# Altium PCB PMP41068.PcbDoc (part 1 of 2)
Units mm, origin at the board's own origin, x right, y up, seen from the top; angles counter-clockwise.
Board outline 71 x 50.75 mm, 4 copper layers (Top Layer, 02IS01, 03IS02, Bottom Layer), stack 0.651 mm thick; 102 components, 48 nets, 246 pads, 360 vias.
Unrouted connection lines stored in the file: 1.
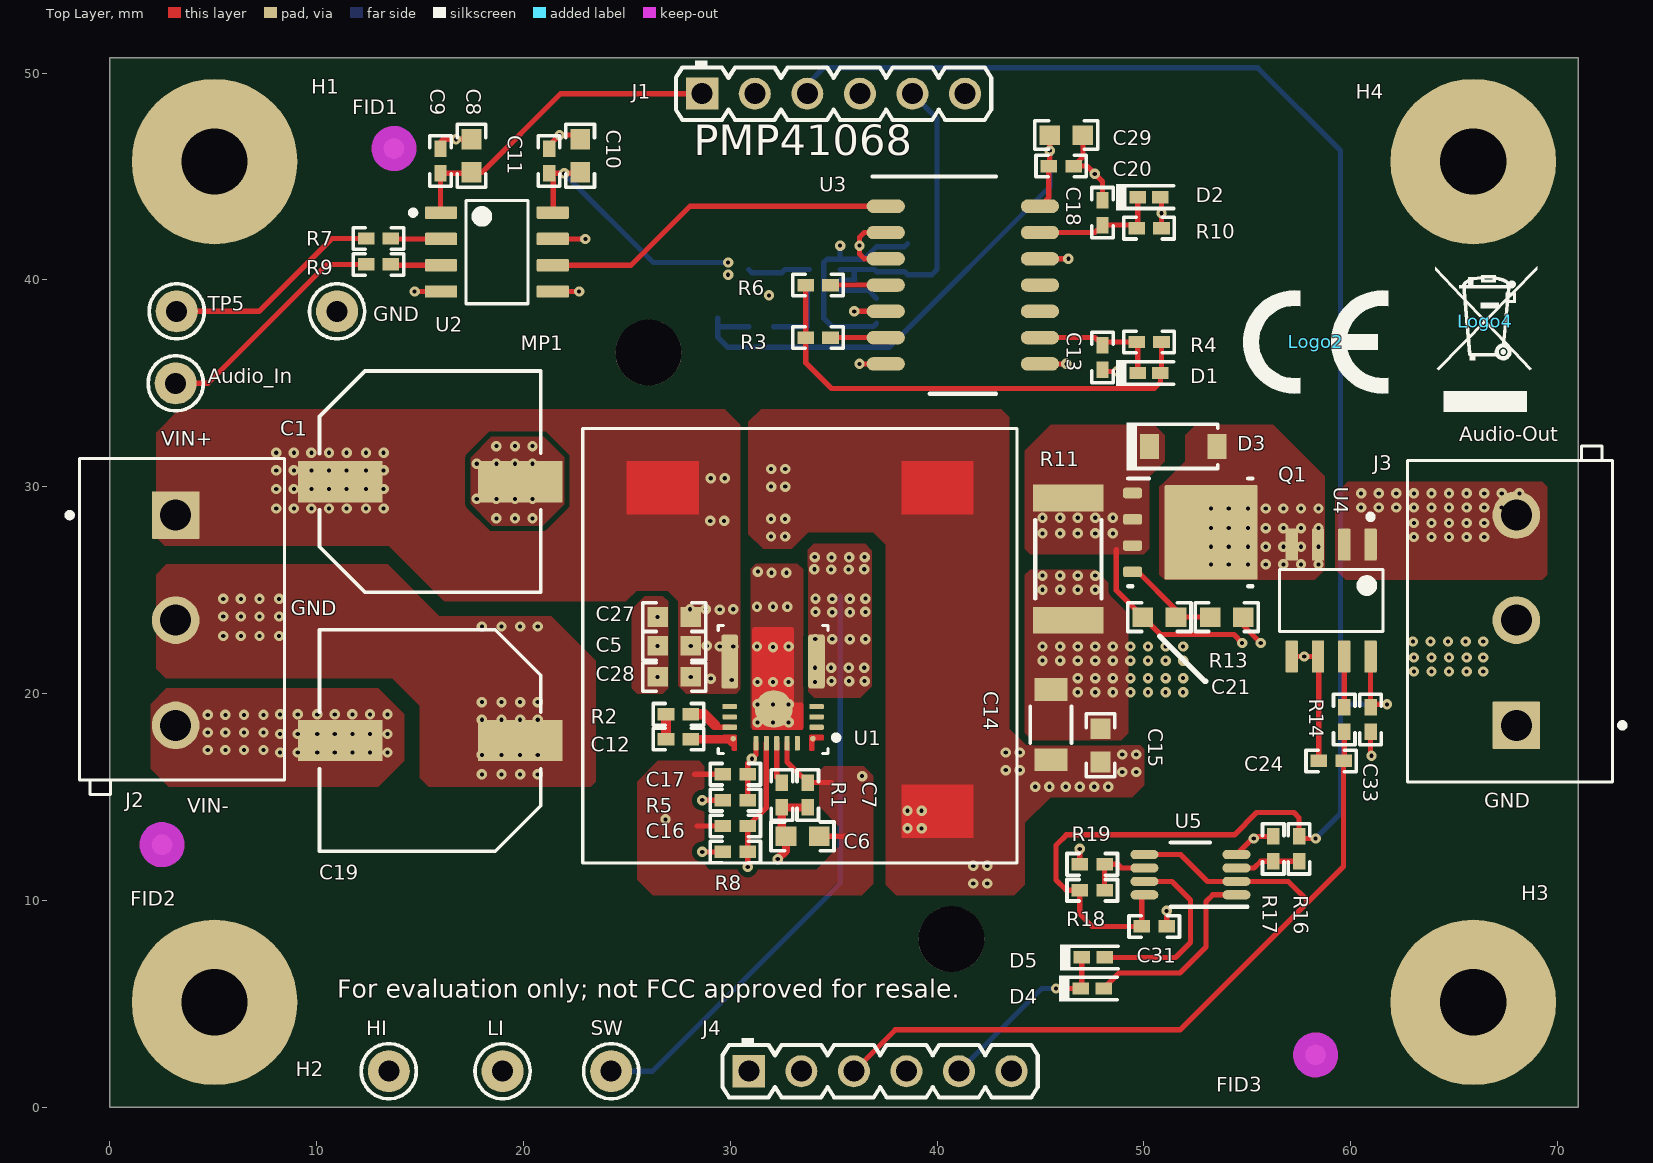
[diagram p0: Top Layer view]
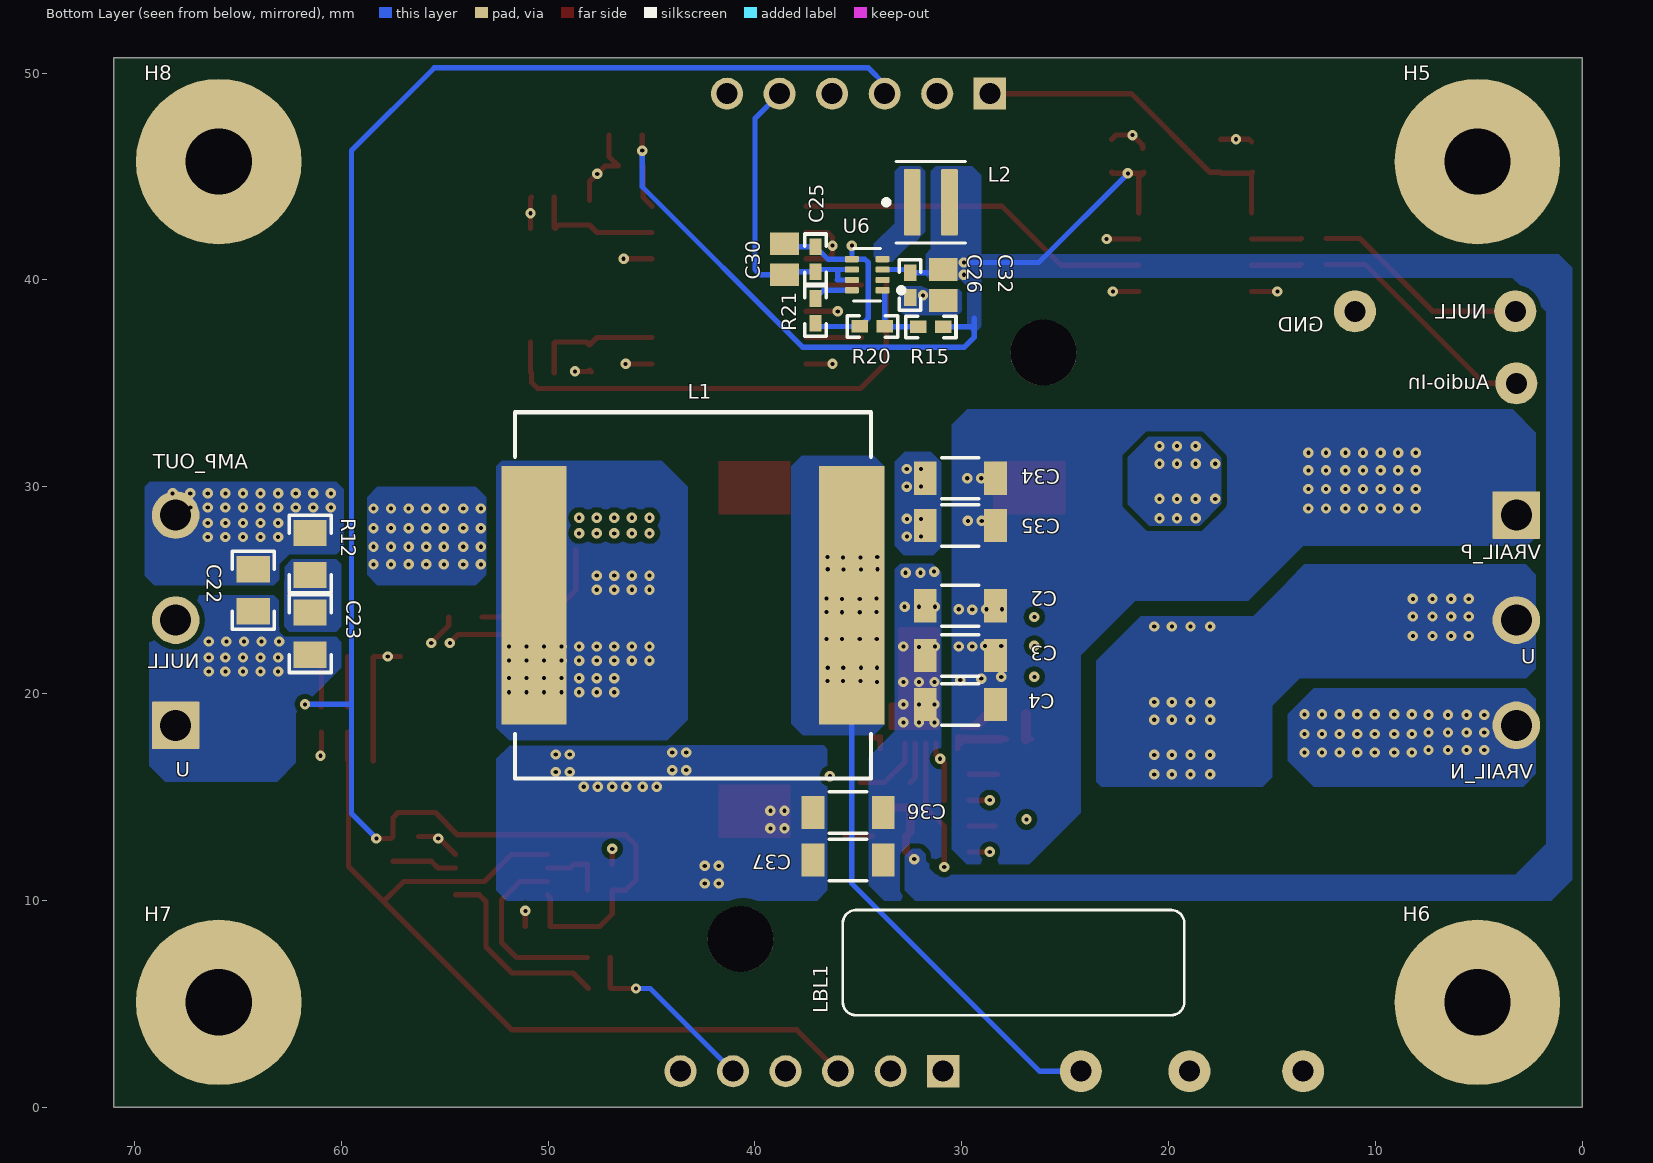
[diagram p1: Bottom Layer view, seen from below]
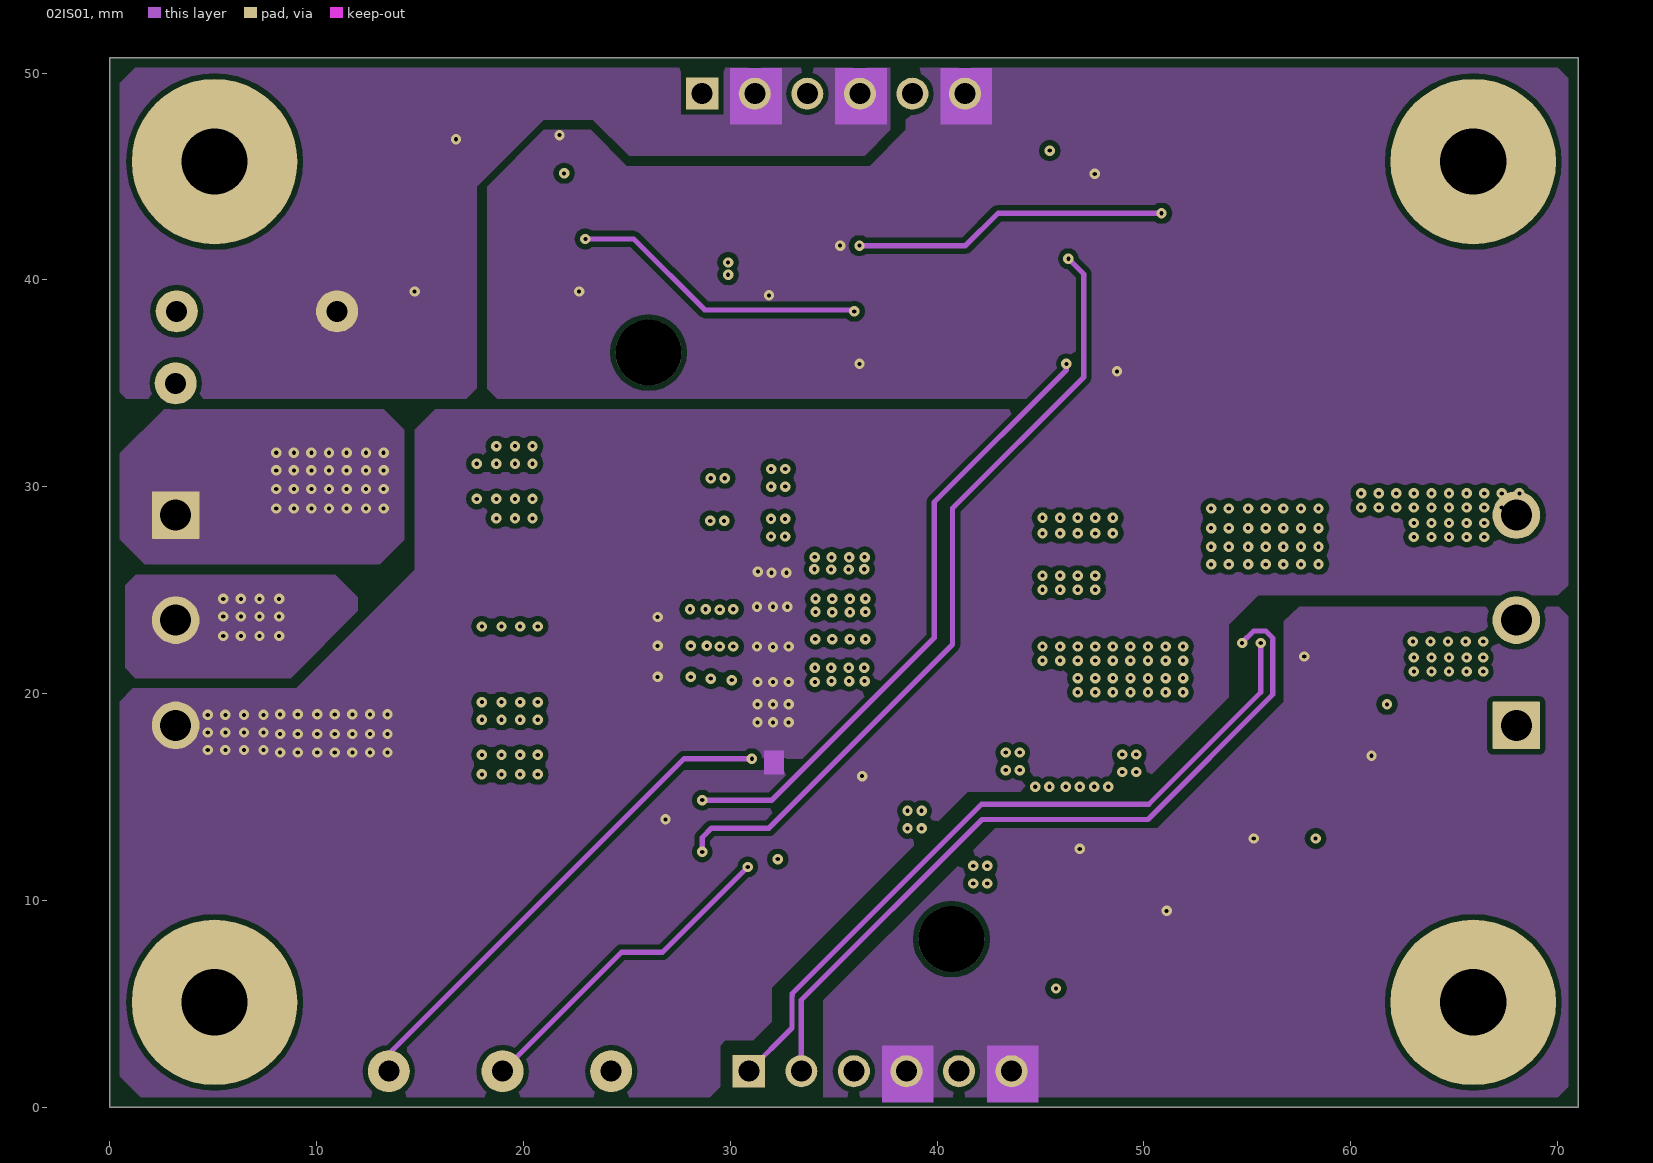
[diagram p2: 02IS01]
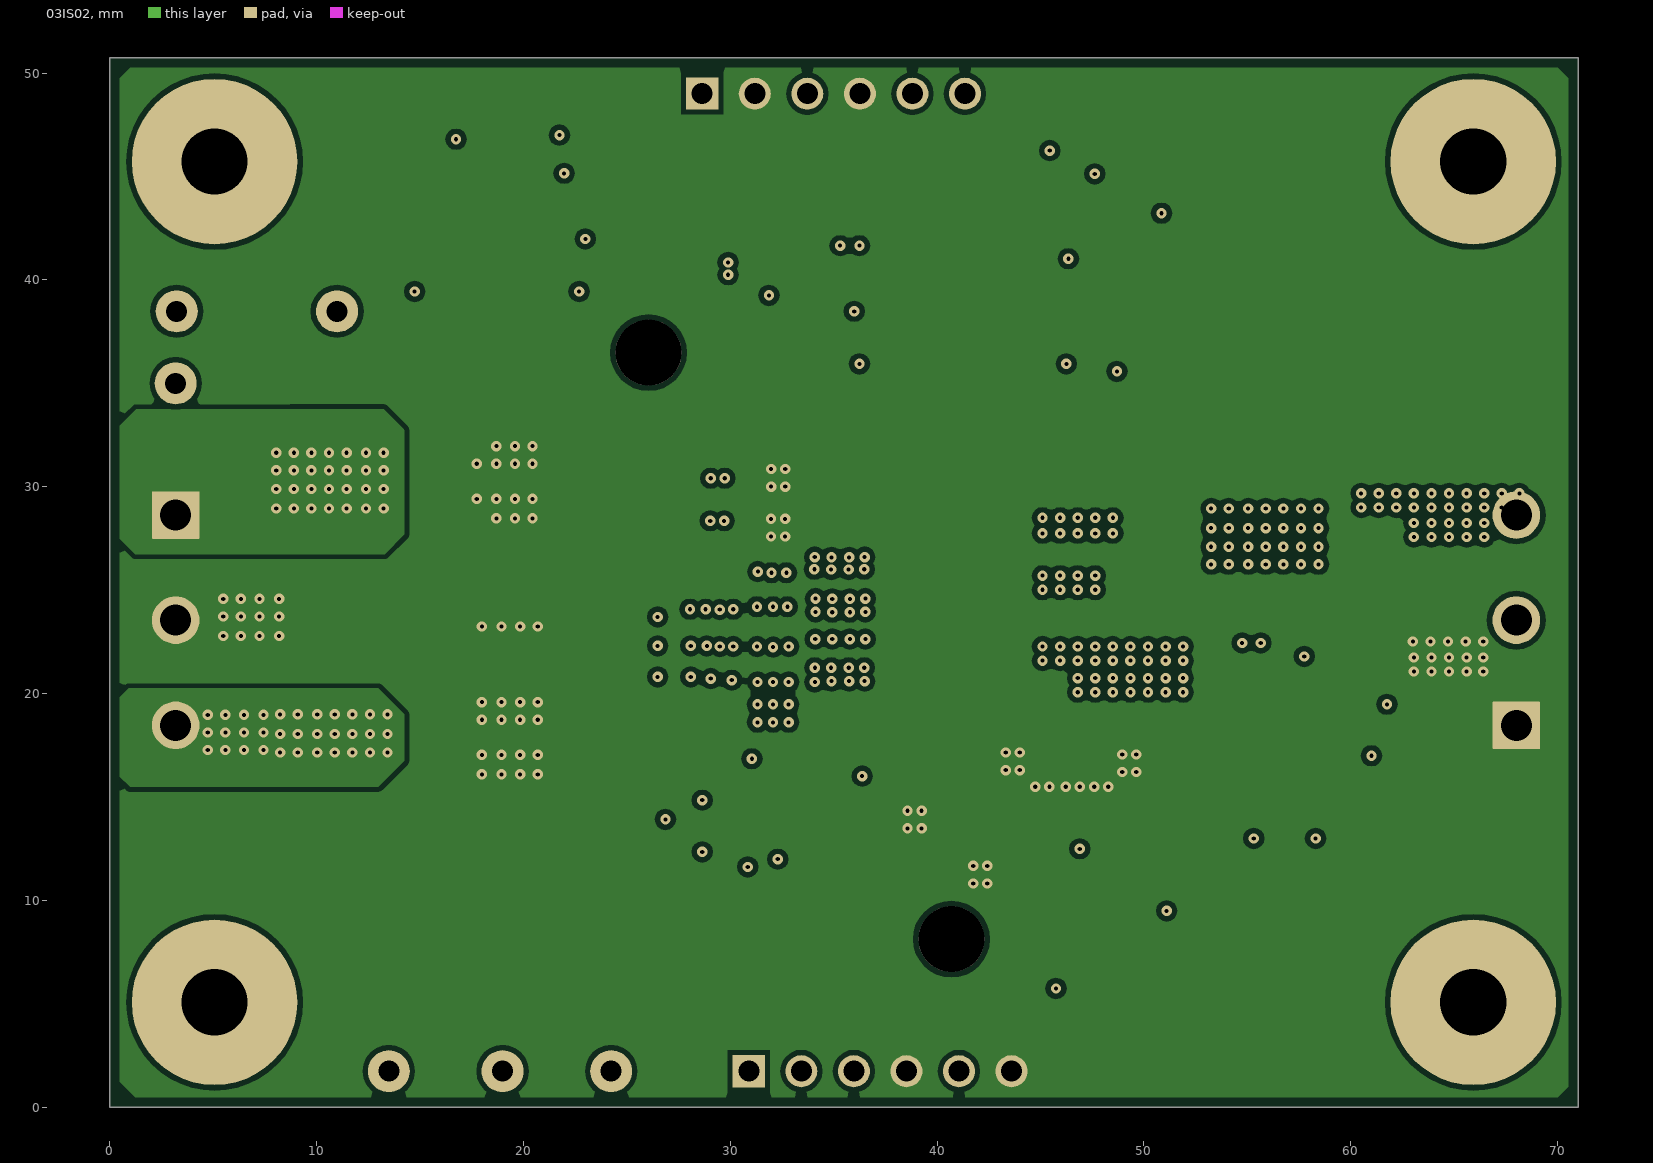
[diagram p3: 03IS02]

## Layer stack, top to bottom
Top Solder: solder mask 0.0102, Solder Resist, Dk 3.5
Top Layer: signal copper 0.0356
Dielectric1: prepreg 0.127, FR-4 High Tg, Dk 4.2
02IS01: signal copper 0.036
Dielectric 2: core 0.254, Dk 4.2
03IS02: signal copper 0.036
Dielectric 3: prepreg 0.127, Dk 4.2
Bottom Layer: signal copper 0.0356
Bottom Solder: solder mask 0.0102, Solder Resist, Dk 3.5

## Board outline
0,0 0,50.75 71,50.75 71,0

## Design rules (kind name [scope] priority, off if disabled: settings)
AcuteAngle [All] p1: minimum=4.50000000000000E+0001 checktracksonly=FALSE
AssemblyTestPointUsage [All] p1: valid=2
Clearance Clearance_BoardEdge_MountingHoles [OnCopper and InComponentClass('Mounting Holes') vs IsKeepOut] p1: gap=1.016 ignorepadtopadclearanceinfootprint=FALSE except(0: Arc-Hole Track-Hole SMDPad-Hole THPad-Hole Via-Hole Fill-Hole Poly-Hole Region-Hole Text-Hole)
Clearance Clearance_BoardEdge_Poly [OnCopper and InPoly vs IsKeepOut] p2: gap=0.635 ignorepadtopadclearanceinfootprint=FALSE except(0: Arc-Hole Track-Hole SMDPad-Hole THPad-Hole Via-Hole Fill-Hole Poly-Hole Region-Hole Text-Hole)
Clearance Clearance_BoardEdge [OnCopper and Not InComponentClass('Logo') and not InComponentClass('FiducialMark') and not InRegion(1000,500,4000,800) and Not IsKeepout vs IsKeepOut] p3: gap=0.127 ignorepadtopadclearanceinfootprint=FALSE except(0: Arc-Hole Track-Hole SMDPad-Hole THPad-Hole Via-Hole Fill-Hole Poly-Hole Region-Hole Text-Hole)
Clearance Clearance_Poly [InPolygon] p4: gap=0.254 ignorepadtopadclearanceinfootprint=FALSE except(0: Arc-Hole Track-Hole SMDPad-Hole THPad-Hole Via-Hole Fill-Hole Poly-Hole Region-Hole Text-Hole)
Clearance [All] p5: gap=0.2 ignorepadtopadclearanceinfootprint=FALSE except(0: Arc-Hole Track-Hole SMDPad-Hole THPad-Hole Via-Hole Fill-Hole Poly-Hole Region-Hole Text-Hole)
ComponentClearance ComponentClearance_Logo [All] p1: gap=0.254 collisioncheckmode=3 verticalgap=0.254 showdistances=TRUE
ComponentClearance ComponentClearance_ScrewToNut [(HasFootprint('NY PMS 440 0025 PH')) vs (HasFootprint('Keystone_1902C'))] p2: gap=0.127 collisioncheckmode=3 verticalgap=0.254 showdistances=FALSE
ComponentClearance ComponentClearance_MountingHoles [InComponentClass('Mounting Holes')] p3: gap=0.254 collisioncheckmode=3 verticalgap=2540 showdistances=FALSE
ComponentClearance ComponentClearance_SmallPassives [HasFootprint('0201*') or HasFootprint('0402*') or HasFootprint('0508') or HasFootprint('0603*') or HasFootprint('0612') or HasFootprint('0805*') or HasFootprint('0815*') or HasFootprint('0830*') or HasFootprint('1206*') or HasFootprint('1210*') or HasFootprint('1808*') or HasFootprint('1812*') or HasFootprint('1825*') or HasFootprint('2010*') or HasFootprint('2220*') or HasFootprint('2225*') or HasFootprint('2512*') or HasFootprint('2728*') or HasFootprint('3518*') vs HasFootprint('0201*') or HasFootprint('0402*') or HasFootprint('0508') or HasFootprint('0603*') or HasFootprint('0612') or HasFootprint('0805*') or HasFootprint('0815*') or HasFootprint('0830*') or HasFootprint('1206*') or HasFootprint('1210*') or HasFootprint('1808*') or HasFootprint('1812*') or HasFootprint('1825*') or HasFootprint('2010*') or HasFootprint('2220*') or HasFootprint('2225*') or HasFootprint('2512*') or HasFootprint('2728*') or HasFootprint('3518*')] p4: gap=0.254 collisioncheckmode=3 verticalgap=0.254 showdistances=FALSE
ComponentClearance ComponentClearance_THtoSMT [IsThruComponent vs IsSMTComponent] p5: gap=0.254 collisioncheckmode=3 verticalgap=2540 showdistances=FALSE
ComponentClearance ComponentClearance_THtoTH [IsThruComponent vs IsThruComponent] p6: gap=0.254 collisioncheckmode=3 verticalgap=2540 showdistances=FALSE
ComponentClearance [All] p7: gap=0.254 collisioncheckmode=3 verticalgap=0.254 showdistances=FALSE
DiffPairsRouting [All] p1: maxlimit=2.54 minlimit=0.254 mostfreqgap=0.254 toplayer_minwidth=0.381 toplayer_maxwidth=0.381 toplayer_prefwidth=0.381 midlayer1_minwidth=0.381 midlayer1_maxwidth=0.381 midlayer1_prefwidth=0.381 midlayer2_minwidth=0.381 midlayer2_maxwidth=0.381 midlayer2_prefwidth=0.381 bottomlayer_minwidth=0.381 bottomlayer_maxwidth=0.381 bottomlayer_prefwidth=0.381 maxuncoupledlength=25.4
FabricationTestPointUsage TestPointUsage [All] p1: valid=2 allowmultiple=FALSE
FabricationTestpoint Testpoint [All] p1: side=3 testpointundercomponent=TRUE minsize=1.016 maxsize=2.54 preferedsize=1.524 minholesize=0 maxholesize=1.016 preferedholesize=0.813 testpointgrid=0.025 allowsidetop=TRUE allowsidebottom=TRUE usegrid=TRUE gridtolerance=0
FanoutControl Fanout_LCC [IsLCC] p1: bgadir=Out bgaviamode=Centered fanoutstyle=Auto fanoutdirection=Alternating viagrid=0.025 // Fanout_LCC (Default Rule)
FanoutControl Fanout_BGA [IsBGA] p2: bgadir=Out bgaviamode=Centered fanoutstyle=Auto fanoutdirection=Alternating viagrid=0.025 // Fanout_BGA (Default Rule)
FanoutControl Fanout_Default [All] p4: bgadir=Out bgaviamode=Centered fanoutstyle=Auto fanoutdirection=Alternating viagrid=0.025 // Fanout_Default (Default Rule)
FanoutControl Fanout_Small [(CompPinCount < 5)] p5: bgadir=Out bgaviamode=Centered fanoutstyle=Auto fanoutdirection=OutThenIn viagrid=0.025 // Fanout_Small (Default Rule)
HoleSize [All] p1: absolutevalues=TRUE maxlimit=6.375 minlimit=0.152 maxpercent=80.000 minpercent=20.000
MinimumAnnularRing [All] p1: minimumring=0.076
MinimumSolderMaskSliver MinimumSolderMaskSliver_Logo [InComponentClass('Logo') vs InComponentClass('Logo')] p1: minsoldermaskwidth=0.018
MinimumSolderMaskSliver [All] p2: minsoldermaskwidth=0
PlaneConnect [All] p1: planeconnectstyle=Direct reliefexpansion=0.254 reliefentries=4 reliefconductorwidth=0.254 reliefairgap=0.254
PolygonConnect [All] p1: connectstyle=Direct reliefconductorwidth=0.254 reliefentries=4 polygonreliefangle="90 Angle" airgapwidth=0.254
RoutingCorners [All] p1: cornerstyle=45-Degree minsetback=0.254 maxsetback=2.54
RoutingVias [All] p1: holewidth=0.406 width=0.864 viastyle="Through Hole" minholewidth=0.203 minwidth=0.406 maxholewidth=1.016 maxwidth=1.651
SMDToCorner [All] p1: distance=0
SilkToSilkClearance [All] p1: silktosilkclearance=0
SilkToSolderMaskClearance SilkscreenOverComponentPads [IsPad] p1: minsilkscreentomaskgap=0 clearancetoexposedcopper=TRUE
SolderMaskExpansion [All] p1: expansion=0.076
Width [All] p1: maxlimit=2.54 minlimit=0.152 preferedwidth=0.254 checkconnectedcopper=TRUE
15 further rules are at their usual default settings.

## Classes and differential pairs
component class Header: J1 J4
component class PMP41068: Audio_In C1 C2 C3 C4 C5 C6 C7 C8 C9 C10 C11 C12 C13 C14 C15 C16 C17 C18 C19 C20 C21 C22 C23 C24 C25 C26 C27 C28 C29 C30 C31 C32 C33 C34 C35 C36 C37 D1 D2 D3 D4 D5 GND HI J1 J2 J3 J4 J6 J7 J8 L1 L2 LI MP1 Q1 R1 R2 R3 R4 R5 R6 R7 R8 R9 R10 R11 R12 R13 R14 R15 R16 R17 R18 R19 R20 R21 SW TP1 TP2 TP3 TP5 U1 U2 U3 U4 U5 U6
component class "Mounting Holes": H1 H2 H3 H4
component class Label: LBL1
component class FiducialMark: FID1 FID2 FID3
component class AssemblyNote: ZZ1 ZZ2 ZZ3 ZZ4
component class PMP41068_Hardware: !PCB FID1 FID2 FID3 H1 H2 H3 H4 H5 H6 H7 H8 LBL1 Logo2 Logo3 Logo4 ZZ1 ZZ2 ZZ3 ZZ4

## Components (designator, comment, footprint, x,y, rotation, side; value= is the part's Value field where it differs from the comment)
Audio_In "5000" Keystone5000 3.2,35 r90 top (schematic designator TP6)
C1 "EEE-FT1H331AP" SM_RADIAL_G 15.5,30.25 r0 top value=330uF
C2 "CGA5L3X7S2A225K160AB" 1206_180 30.075,24.25 r0 bottom value=2.2uF
C3 "CGA5L3X7S2A225K160AB" 1206_180 30.075,21.852 r0 bottom value=2.2uF
C4 "CGA5L3X7S2A225K160AB" 1206_180 30.075,19.484 r0 bottom value=2.2uF
C5 "GCJ188R72A104KA01D" 0603 27.296,22.31 r180 top value=0.1uF
C6 "GCM188R71E105KA64D" 0603 33.5,13.102 r0 top value=1uF
C7 "CGA2B3X7R1E104K050BB" 0402 33.75,15.102 r90 top value=0.1uF
C8 "GCM188R71E105KA64D" 0603 17.5,46 r90 top value=1uF
C9 "CGA2B3X7R1E104K050BB" 0402 16,45.75 r90 top value=0.1uF
C10 "GCM188R71E105KA64D" 0603 22.75,46 r90 top value=1uF
C11 "CGA2B3X7R1E104K050BB" 0402 21.25,45.75 r90 top value=0.1uF
C12 "CGA2B3X7R1E104K050BB" 0402 27.5,17.802 r0 top value=0.1uF
C13 "GCM1555C1H100JA16D" 0402 48,36.25 r270 top value=10pF
C14 "CGA5L3X7S2A225K160AB" 1206_180 45.5,18.5 r270 top value=2.2uF
C15 "GCJ188R72A104KA01D" 0603 47.9,17.5 r270 top value=0.1uF
C16 "GCM1555C1H100JA16D" 0402 30.25,13.602 r180 top value=10pF
C17 "GCM1555C1H100JA16D" 0402 30.25,16.102 r180 top value=10pF
C18 "GCM1555C1H100JA16D" 0402 48,43.25 r90 top value=10pF
C19 "EEE-FT1H331AP" SM_RADIAL_G 15.5,17.735 r180 top value=330uF
C20 "CGA2B3X7R1E104K050BB" 0402 46,45.5 r0 top value=0.1uF
C21 "GCM188R71E105KA64D" 0603 50.75,23.7 r0 top value=1uF
C22 "GRM21AR72E102KW01D" 0805_HV 64.25,25 r270 bottom value=1000pF
C23 "CGA4J3C0G2E103J125AA" 0805_HV 61.5,22.902 r270 bottom value=0.01uF
C24 "GCM1555C1H100JA16D" 0402 59.05,16.75 r180 top value=10pF
C25 "CGA2B3X7R1E104K050BB" 0402 37.075,41 r90 bottom value=0.1uF
C26 "CGA2B3X7R1E104K050BB" 0402 32.5,39.75 r270 bottom value=0.1uF
C27 "GCJ188R72A104KA01D" 0603 27.296,23.708 r180 top value=0.1uF
C28 "GCJ188R72A104KA01D" 0603 27.296,20.81 r180 top value=0.1uF
C29 "GCM188R71E105KA64D" 0603 46.25,47 r0 top value=1uF
C30 "CGA4J1X7R1E475K125AC" 0805L 38.575,41 r90 bottom value=4.7uF
C31 "CGA2B3X7R1E104K050BB" 0402 50.5,8.75 r0 top value=0.1uF
C32 "CGA4J1X7R1E475K125AC" 0805L 30.9,39.75 r270 bottom value=4.7uF
C33 "CGA2B3X7R1E104K050BB" 0402 60.955,18.75 r270 top value=0.1uF
C34 "CGA5L3X7S2A225K160AB" 1206_180 30.075,30.412 r0 bottom value=2.2uF
C35 "CGA5L3X7S2A225K160AB" 1206_180 30.075,28.127 r0 bottom value=2.2uF
C36 "CGA5L3X7S2A225K160AB" 1206_180 35.5,14.25 r180 bottom value=2.2uF
C37 "CGA5L3X7S2A225K160AB" 1206_180 35.5,11.952 r180 bottom value=2.2uF
D1 "SDM03U40-7" SOD-523 50.25,35.5 r0 top value=40V
D2 "SDM03U40-7" SOD-523 50.25,44 r0 top value=40V
D3 "SM4007PL-TP" SOD-123FL 51.9,31.95 r0 top value=1000V
D4 "SDM03U40-7" SOD-523 47.5,5.75 r0 top value=40V
D5 "SDM03U40-7" SOD-523 47.55,7.25 r0 top value=40V
FID1 "Fiducial" Fiducial10-20 13.75,46.35 r0 top
FID2 "Fiducial" Fiducial10-20 2.54,12.7 r0 top
FID3 "Fiducial" Fiducial10-20 58.3,2.54 r0 top
GND "5000" Keystone5000 11,38.48 r90 top (schematic designator TP4)
H1 "NY PMS 440 0025 PH" "NY PMS 440 0025 PH" 5.08,45.72 r0 top
H2 "NY PMS 440 0025 PH" "NY PMS 440 0025 PH" 5.08,5.08 r0 top
H3 "NY PMS 440 0025 PH" "NY PMS 440 0025 PH" 65.92,5.08 r0 top
H4 "NY PMS 440 0025 PH" "NY PMS 440 0025 PH" 65.92,45.72 r0 top
H5 "1902C" Keystone_1902C 5.08,45.72 r180 bottom
H6 "1902C" Keystone_1902C 5.089,5.08 r180 bottom
H7 "1902C" Keystone_1902C 65.92,5.08 r180 bottom
H8 "1902C" Keystone_1902C 65.929,45.72 r180 bottom
HI "5000" Keystone5000 13.5,1.75 r90 top (schematic designator TP2)
J1 "PBC06SAAN" Sullins_PxC06SAAN 35,49 r0 top
J2 "691216510003S" FP-691216510003S_CONN_TERM_BLOCK3-MFG 3.5,23.25 r270 top
J3 "691216510003S" FP-691216510003S_CONN_TERM_BLOCK3-MFG 67.7,23.85 r90 top
J4 "PBC06SAAN" Sullins_PxC06SAAN 37.25,1.75 r0 top
L1 "PA4344.103NLT" PA4344 43,24.75 r270 bottom value=10uH
L2 "XGL3530-332MEC" FP-XGL3530_SMT_IND_3MM2_3MM5-MFG 31.5,43.75 r180 bottom value=3.3uH
LBL1 "THT-14-423-10" Label_650x200 27.5,7 r0 bottom
LI "5000" Keystone5000 19,1.75 r90 top (schematic designator TP3)
Logo2 "CE Mark" CE_Mark_5mm 58.3,37 r0 top
Logo3 "FCC disclaimer" FCC_disclaimer 87.25,39 r0 top
Logo4 "WEEE logo" WEEE_Minimum 66.5,38 r0 top
MP1 "960-21-12-S-AB-0" FP-960-21-12-S-AB-0_HEATSINK_BGA_21MM_12MM-MFG 33.375,22.31 r90 top
Q1 "CSD17581Q5A" DQJ0008A 52.245,27.795 r0 top value=30V
R1 "CRCW04024R70JNED" 0402 32.5,15.102 r270 top value=4.7
R2 "CRCW04024R70JNED" 0402 27.5,19 r180 top value=4.7
R3 "CRCW04020000Z0ED" 0402 34.25,37.21 r180 top value=0
R4 "CRCW040247R0JNED" 0402 50.25,37 r180 top value=47
R5 "RMCF0402JT10R0" 0402 30.25,14.852 r0 top value=10.0
R6 "CRCW04020000Z0ED" 0402 34.25,39.75 r180 top value=0
R7 "CRCW04020000Z0ED" 0402 13,42 r0 top value=0
R8 "RMCF0402JT10R0" 0402 30.25,12.352 r0 top value=10.0
R9 "CRCW04020000Z0ED" 0402 13,40.75 r0 top value=0
R10 "CRCW040247R0JNED" 0402 50.25,42.5 r180 top value=47
R11 "CRCW25120000Z0EGHP" 2512 46.35,26.5 r90 top value=0
R12 "CRCW08053R30JNEA" 0805_HV 61.5,26.75 r90 bottom value=3.3
R13 "CRCW0603200KFKEA" 0603 54,23.7 r180 top value=200k
R14 "CRCW04020000Z0ED" 0402 59.685,18.75 r90 top value=0
R15 "CRCW0402619KFKED" 0402 31.5,37.73 r180 bottom value=619k
R16 "CRCW040225K5FKED" 0402 57.5,12.5 r90 top value=25.5k
R17 "CRCW040212K0FKED" 0402 56.25,12.5 r270 top value=12.0k
R18 "CRCW04025K60JNED" 0402 47.5,10.5 r180 top value=5.6k
R19 "CRCW040212K0FKED" 0402 47.5,11.75 r0 top value=12.0k
R20 "CRCW040284K5FKED" 0402 34.325,37.75 r180 bottom value=84.5k
R21 "CRCW040217K8FKED" 0402 37.075,38.5 r90 bottom value=17.8k
SW "5000" Keystone5000 24.25,1.75 r90 top (schematic designator TP1)
TP5 "5000" Keystone5000 3.25,38.48 r90 top
U1 "LMG2100R044" RAR0016A-MFG 32.075,20.202 r180 top
U2 "ISO6720BDR" D0008A-MFG 18.725,41.345 r0 top
U3 "SN74AC14NSR" NS0014A_M 41.25,39.75 r0 top
U4 "TMCS1108A1BQDR" D0008A-MFG 59.05,24.5 r270 top
U5 "TLV7032QDGKRQ1" DGK0008A_N 52.25,11.25 r180 top
U6 "TPS629210QDRLRQ1" DRL0008A-MFG 34.575,40.25 r0 bottom
ZZ1 "This Assembly Note is for PCB labels only" AssemblyNoteLabel 0,60.96 r0 top
ZZ2 "These assemblies are ESD sensitive, ESD precautions shall be observed." AssemblyNote 0,58.42 r0 top
ZZ3 "These assemblies must be clean and free from flux and all contaminants. Use of no clean flux is not acceptable." AssemblyNote 0,55.88 r0 top
ZZ4 "These assemblies must comply with workmanship standards IPC-A-610 Class 2, unless otherwise specified." AssemblyNote 0,53.34 r0 top

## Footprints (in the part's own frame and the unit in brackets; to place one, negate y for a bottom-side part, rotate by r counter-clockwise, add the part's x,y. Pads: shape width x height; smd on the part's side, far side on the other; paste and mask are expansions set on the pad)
0402 [mm] "0402 from SM-752 data"
  rect 0.8x0.6 smd: 1(-0.6,0) 2(0.6,0)
  silkscreen extent -1.22,-0.52 1.22,0.52, body extent -0.55,-0.3 0.55,0.3, height 0.6
0603 [mm] "0603 from SM-752 data"
  rect 1x0.95 smd: 1(-0.8,0) 2(0.8,0)
  silkscreen extent -1.52,-0.69 1.52,0.69, body extent -0.87,-0.47 0.87,0.47, height 1
0805_HV [mil] "0805 with 30mil clearance between pads"
  rect 50x63 smd: 1(-40,0) 2(40,0)
  silkscreen extent -74,-40 74,40, body extent -43,-29 43,29, height 57
0805L [mm] "0805 from SM-752 data"
  rect 1.1x1.4 smd: 1(-0.75,0) 2(0.75,0)
  body extent -1.1,-0.72 1.1,0.72, height 1.45
1206_180 [mm] "1206_180"
  rect 1.1x1.6 smd: 1(-1.7,0) 2(1.7,0)
  silkscreen extent -0.9,-1 0.9,1, body extent -1.75,-0.95 1.75,0.95, height 1.8
2512 [mm] "Chip Resistor, Body 6.3x3.2mm, IPC Medium Density"
  rect 1.3x3.4 smd: 1(-2.95,0) 2(2.95,0)
  silkscreen extent -1.9,-1.6 1.9,1.6, body extent -3.22,-1.67 3.22,1.67, height 0.71
AssemblyNote [mm] "Assembly Note"
AssemblyNoteLabel [mm] "Assembly Note for PCB Labels"
CE_Mark_5mm [mm] "Minimum text height for CE Mark"
  silkscreen extent -3.5,-2.5 3.5,2.5
D0008A-MFG [mm]
  rrect17% 1.55x0.6 smd paste+0 mask+0: 1(-2.7,1.905) 2(-2.7,0.635) 3(-2.7,-0.635) 4(-2.7,-1.905) 5(2.7,-1.905) 6(2.7,-0.635) 7(2.7,0.635) 8(2.7,1.905)
  silkscreen extent -4.17,-2.5 1.5,2.5, body extent -3.57,-2.75 3.57,2.75, height 0.25
DGK0008A_N [mm] "TSOP, 8-Leads, Body 3x3mm, Pitch 0.65mm, IPC Medium Density"
  oval 1.35x0.45 smd: 1(-2.225,0.975) 2(-2.225,0.325) 3(-2.225,-0.325) 4(-2.225,-0.975) 5(2.225,-0.975) 6(2.225,-0.325) 7(2.225,0.325) 8(2.225,0.975)
  silkscreen extent -2.75,-1.55 0.95,1.55, body extent -2.45,-1.5 2.45,1.5, height 0.96
DQJ0008A [mm] "SMD, 8-Leads, Body 5.75x4.9mm"
  rrect39% 0.91x0.51 smd paste-0.05 mask-0.05: 1(-2.795,1.905) 2(-2.795,0.635) 3(-2.795,-0.635) 4(-2.795,-1.905) 5(2.795,-1.905) 6(2.795,-0.635) 7(2.795,0.635) 8(2.795,1.905)
  rrect8% 1.58x1.25 on Top Paste: 9(-0.38,-1.45) 9(-0.38,0) 9(-0.38,1.45) 9(1.4,-1.45) 9(1.4,0) 9(1.4,1.45)
  rrect3% 3.48x4.47 on Top Solder: 9(0.55,0)
  rrect2% 4.49x4.57 smd paste-2.5 mask-2.5: 9(1.005,0)
  silkscreen extent -3,-2.6 3,2.6, body extent -3.13,-2.45 3.13,2.45, height 1.15
DRL0008A-MFG [mm]
  rrect33% 0.67x0.3 smd paste+0 mask+0: 1(-0.74,0.75) 2(-0.74,0.25) 3(-0.74,-0.25) 4(-0.74,-0.75) 5(0.74,-0.75) 6(0.74,-0.25) 7(0.74,0.25) 8(0.74,0.75)
  silkscreen extent -1.77,-1.28 0.65,1.28, body extent -0.8,-1.05 0.8,1.05, height 0.6
FCC_disclaimer [mm]
Fiducial10-20 [mm]
  round 1 smd mask+0.5: 1(0,0)
  Top Layer keep-out circle w1.178: c0,0 r0.5
FP-960-21-12-S-AB-0_HEATSINK_BGA_21MM_12MM-MFG [mm]
  round 3.18 hole 3.18 unplated paste-1000 mask+0: ""(-14.175,-7.32) ""(14.175,7.32)
  silkscreen extent -10.5,-10.5 10.5,10.5, body extent -17.7,-10.85 17.7,10.85, height 0.25
FP-691216510003S_CONN_TERM_BLOCK3-MFG [mm]
  rrect4% 2.3x2.3 hole 1.5 paste-1000 mask+0: 1(-5.38,-0.3)
  round 2.3 hole 1.5 paste-1000 mask+0: 2(-0.3,-0.3) 3(4.78,-0.3)
  silkscreen extent -8.12,-5.55 8.13,4.95, body extent -8.22,-5.05 8.22,5.05, height 0.25
FP-XGL3530_SMT_IND_3MM2_3MM5-MFG [mm]
  rrect12% 0.81x3.2 smd paste+0 mask+0: 1(-0.9,0) 2(0.9,0)
  silkscreen extent -2.28,-1.97 1.68,1.97, body extent -1.6,-1.75 1.6,1.75, height 3
Keystone5000 [mil] "For Keystone 500x miniature loop terminals"
  round 80 hole 40: 1(0,0)
  silkscreen extent -52,-52 52,52, body extent -49,-49 49,49, height 182
Keystone_1902C [mil] "Hex Standoff, 4-40 threaded, nylon"
  round 1 on Mech3: 0(0,0)
  body extent -145,-126 146,126, height 501
Label_650x200 [mil] "Thermal Transfer Label"
  round 1 on Mech13: 0(0,0)
  silkscreen extent -325,-100 325,100, body extent -325,-100 325,100, height 1
NS0014A_M [mm] "SOP, 14-Leads, Body 10.2x5.3mm, Pitch 1.27mm, IPC Low Density"
  oval 1.85x0.65 smd: 1(-3.725,3.81) 2(-3.725,2.54) 3(-3.725,1.27) 4(-3.725,0) 5(-3.725,-1.27) 6(-3.725,-2.54) 7(-3.725,-3.81) 8(3.725,-3.81) 9(3.725,-2.54) 10(3.725,-1.27) 11(3.725,0) 12(3.725,1.27) 13(3.725,2.54) 14(3.725,3.81)
  silkscreen extent -4.38,-5.25 1.6,5.25, body extent -3.91,-5.1 3.91,5.1, height 2
"NY PMS 440 0025 PH" [mm] "4-40 nylon screw and mounting hole"
  round 8 hole 3.2: 1(0,0)
  body extent -3.3,-3.3 3.3,3.3, height 2.69
PA4344 [mm] "SMD, 2-Leads, Body 17.7x17.2mm"
  rect 12.5x3.15 smd: 1(0,7.675) 2(0,-7.675)
  silkscreen extent -8.85,-8.6 8.85,8.6, body extent -8.85,-8.6 8.85,8.6, height 7
RAR0016A-MFG [mm]
  round 0.265 smd paste+0 mask-1000: 1(-1.925,2.375) 11(1.925,2.375)
  rrect40% 0.7x0.25 smd paste+0 mask-1000: 2(-2.1,1.825) 3(-2.1,1.325) 4(-2.1,0.825) 8(2.1,0.825) 9(2.1,1.325) 10(2.1,1.825)
  rrect25% 0.8x2.6 smd paste-1000 mask-1000: 5(-2.1,-1.35) 7(2.1,-1.35)
  round 1.813 smd paste-1000 mask-1000: 6(-0.034,0.943)
  rrect40% 0.25x0.7 smd paste+0 mask-1000: 12(0.825,2.6) 13(0.325,2.6) 14(-0.175,2.6) 15(-0.675,2.6) 16(-1.175,2.6)
  Top Layer region: -2.4,2.2 -2.419,2.204 -2.435,2.215 -2.446,2.231 -2.45,2.25 -2.45,2.25 -2.45,2.4 -2.443,2.425 -2.425,2.443 -2.4,2.45 -2.4,2.45 -2.1,2.45 -2.062,2.458 -2.029,2.479 -2.008,2.512 -2,2.55 -2,2.55 -2,2.9 -1.993,2.925 -1.975,2.943 -1.95,2.95 -1.95,2.95 -1.8,2.95 -1.781,2.946 -1.765,2.935 -1.754,2.919 -1.75,2.9 -1.75,2.9 -1.75,2.25 -1.754,2.231 -1.765,2.215 -1.781,2.204 -1.8,2.2 -1.8,2.2
  Top Layer region: 2.4,2.2 2.419,2.204 2.435,2.215 2.446,2.231 2.45,2.25 2.45,2.25 2.45,2.4 2.443,2.425 2.425,2.443 2.4,2.45 2.4,2.45 2.1,2.45 2.062,2.458 2.029,2.479 2.008,2.512 2,2.55 2,2.55 2,2.9 1.993,2.925 1.975,2.943 1.95,2.95 1.95,2.95 1.8,2.95 1.775,2.943 1.757,2.925 1.75,2.9 1.75,2.9 1.75,2.25 1.754,2.231 1.765,2.215 1.781,2.204 1.8,2.2 1.8,2.2
  Top Layer region: -1.45,1.85 -1.437,1.9 -1.4,1.937 -1.35,1.95 -1.35,1.95 0.9,1.95 0.938,1.942 0.971,1.921 0.992,1.888 1,1.85 1,1.85 1,-2.9 0.987,-2.95 0.95,-2.987 0.9,-3 0.9,-3 -0.9,-3 -0.95,-2.987 -0.987,-2.95 -1,-2.9 -1,-2.9 -1,0.585 -1.004,0.604 -1.015,0.62 -1.031,0.631 -1.05,0.635 -1.05,0.635 -1.35,0.635 -1.388,0.643 -1.421,0.664 -1.442,0.697 -1.45,0.735 -1.45,0.735
  silkscreen extent -3.17,-3.1 2.65,3.1, body extent -2.6,-3.1 2.6,3.05, height 0.25
SM_RADIAL_G [mm] "10 x 10.2mm:  Panasonic G"
  rect 4.1x2 smd: 1(-4.35,0) 2(4.35,0)
  silkscreen extent -5.35,-5.35 5.35,5.35, body extent -5.25,-5.25 5.25,5.25, height 10.5
SOD-123FL [mm] "Copied from SOD-123"
  rect 0.915x1.22 smd: 1(-1.637,0) 2(1.637,0)
  silkscreen extent -2.74,-1.16 1.68,1.16, body extent -1.9,-0.9 1.9,0.9, height 1
SOD-523 [mm] "NXP Semiconductor recommended land pattern, nominal STEP model"
  rect 0.8x0.6 smd paste-0.05: 1(-0.55,0) 2(0.55,0)
  silkscreen extent -1.6,-0.63 1.2,0.64, body extent -0.8,-0.4 0.8,0.4, height 0.72
Sullins_PxC06SAAN [mm] "Header, 2.54mm, 6x1, TH"
  rect 1.55x1.55 hole 1.016: 1(-6.35,0)
  round 1.55 hole 1.016: 2(-3.81,0) 3(-1.27,0) 4(1.27,0) 5(3.81,0) 6(6.35,0)
  silkscreen extent -7.62,-1.27 7.62,1.6, body extent -7.62,-1.27 7.62,1.27, height 8.38
WEEE_Minimum [mm] "WEEElie bin"
  silkscreen extent -2.42,-4.38 2.52,2.65

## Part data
Audio_In GND HI LI SW TP5: library part CMP-0055137-2, "Test Point, Miniature, Red, TH", Color=Red, Manufacturer="Keystone Electronics", Supplier Part Number 1=36-5000-ND
C1 C19: library part CMP-0860442-1, "CAP, AL, 330 µF, 50 V, +/- 20%, 0.12 ohm, AEC-Q200 Grade 2, SMD", Cap_Case=10x10.2mm, Manufacturer=Panasonic, Tolerance_%=20%, Value1="0.12 ohm", Value2=50V, ValueDisplayed=330µF
C2 C3 C4 C14 C34 C35 C36 C37: library part CMP-0008790-2, "CAP, CERM, 2.2 uF, 100 V, +/- 10%, X7S, AEC-Q200 Grade 1, 1206", Cap_Case=1206_180, Manufacturer=TDK, Supplier Part Number 1=445-6994-1-ND, Tempco=X7S, Tolerance_%=10%, Value1="0.005718 ohm", Value2=100V, ValueDisplayed=2.2uF
C5 C15 C27 C28: library part CMP-0064935-2, "CAP, CERM, 0.1 uF, 100 V,+/- 10%, X7R, AEC-Q200 Grade 1, 0603", Cap_Case=0603, Manufacturer=MuRata, Supplier Part Number 1=490-13420-1-ND, Tempco=X7R, Tolerance_%=10%, Value1=Unknown, Value2=100V, ValueDisplayed=0.1uF
C6 C8 C10 C21 C29: library part CMP-0007139-1, "CAP, CERM, 1 uF, 25 V, +/- 10%, X7R, AEC-Q200 Grade 1, 0603", Cap_Case=0603, Manufacturer=MuRata, Supplier Part Number 1=490-10673-1-ND, Tempco=X7R, Tolerance_%=10%, Value1=Unknown, Value2=25V, ValueDisplayed=1uF
C7 C9 C11 C12 C20 C25 C26 C31 C33: library part CMP-0080610-1, "CAP, CERM, 0.1 µF, 25 V,+/- 10%, X7R, AEC-Q200 Grade 1, 0402", Cap_Case=0402, Manufacturer=TDK, Supplier Part Number 1=445-6902-1-ND, Tempco=X7R, Tolerance_%=10%, Value2=25V, ValueDisplayed=0.1µF
C13 C16 C17 C18 C24: library part CMP-0860290-1, "CAP, CERM, 10 pF, 50 V,+/- 5%, C0G/NP0, AEC-Q200 Grade 1, 0402", Cap_Case=0402, Manufacturer=MuRata, Tempco=C0G/NP0, Tolerance_%=5%, Value2=50V, ValueDisplayed=10pF
C22: library part CMP-0008251-2, "CAP, CERM, 1000 pF, 250 V, +/- 10%, X7R, 0805", Cap_Case=0805, Manufacturer=MuRata, Supplier Part Number 1=490-3525-1-ND, Tempco=X7R, Tolerance_%=10%, Value1=Unknown, Value2=250V, ValueDisplayed=1000pF
C23: library part CMP-0007972-1, "CAP, CERM, 0.01 uF, 250 V, +/- 5%, C0G/NP0, AEC-Q200 Grade 1, 0805", Cap_Case=0805, Manufacturer=TDK, Supplier Part Number 1=445-15561-1-ND, Tempco=C0G/NP0, Tolerance_%=5%, Value1=Unknown, Value2=250V, ValueDisplayed=0.01uF
C30 C32: library part CMP-0076706-1, "CAP, CERM, 4.7 µF, 25 V,+/- 10%, X7R, AEC-Q200 Grade 1, 0805", Cap_Case=2x1.25x1.25mm, Manufacturer=TDK, Supplier Part Number 1=445-6967-1-ND, Tempco=X7R, Tolerance_%=10%, Value2=25V, ValueDisplayed=4.7µF
D1 D2 D4 D5: library part CMP-0028563-1, "Diode, Schottky, 40 V, 0.03 A, SOD-523", Manufacturer="Diodes Inc.", Supplier Part Number 1=SDM03U40DICT-ND, Value1=0.03A, Value2=1V
D3: library part CMP-0077021-2, "Diode, Standard Recovery Rectifier, 1000 V, 1 A, SOD-123FL", Manufacturer="Micro Commercial Components", Value1=1A, Value2=1.1V
FID1 FID2 FID3: library part CMP-0077181-1, "Fiducial mark.  There is nothing to buy or mount.", Manufacturer=N/A
H1 H2 H3 H4: library part CMP-0003617-1, "Machine Screw, Round, #4-40 x 1/4, Nylon, Philips panhead", Manufacturer="B&F Fastener Supply", Supplier Part Number 1=H542-ND
H5 H6 H7 H8: library part CMP-0003610-1, "Standoff, Hex, 0.5\"L #4-40 Nylon", Manufacturer=Keystone, Supplier Part Number 1=36-1902C-ND
J1 J4: library part CMP-0054603-1, "Header, 2.54mm, 6x1, Gold, TH", Color=Black, Current_A=3A, Manufacturer="Sullins Connector Solutions", Supplier Part Number 1=S1011E-06-ND
J2 J3: library part CMP-0096886-1, Current_A=14A, Digikey Part Number=732-691216510003S-ND, Manufacturer="Wurth Electronics", Mouser Part Number=710-691216510003S, Operating Temperature Range="-30°C to +120°C", Voltage_V=300V
L1: library part CMP-0062096-1, "Inductor, Shielded, 10 uH, 16.5 A, 0.013 ohm, AEC-Q200 Grade 1, SMD", Manufacturer="Pulse Engineering", Supplier Part Number 1=553-3010-1-ND, Value1="0.013 ohm", Value2=16.5A, ValueDisplayed=10uH
L2: library part CMP-0092762-2, "Power Inductor, shielded, composite, 20% tol, SMT, RoHS, halogen-free   USD 0.580", Manufacturer=Coilcraft, Operating Temperature Range="to +165°C", Self Resonant Frequency=43MHz, Test Frequency=1MHz, Tolerance_%=20%
LBL1: library part CMP-0003625-1, "Thermal Transfer Printable Labels, 0.650\" W x 0.200\" H - 10,000 per roll", Manufacturer=Brady, Supplier Part Number 1=97C5133
Logo2: library part CMP-0074844-1
Logo3: library part CMP-0074847-1, "FCC_disclaimer"
Logo4: library part CMP-0074769-1
MP1: library part CMP-0090374-1, "HEATSINK 21X12MM SIDE PLASTIC PUSH PIN", Digikey Part Number=345-1764-ND, Manufacturer=Wakefield-Vette, Mating Package=BGA, Mouser Part Number=567-960-21-12-S-AB-0, Operating Temperature Range=to
Q1: library part CMP-0071234-1, "MOSFET, N-CH, 30 V, 24 A, DQJ0008A (VSONP-8)", Alternate Manufacturer=None, Manufacturer="Texas Instruments", Supplier Part Number 1=CSD17581Q5A-ND, Value1="0.0042 ohm", Value2="20 nC"
R1 R2: library part CMP-0026942-3, "RES, 4.7, 5%, 0.063 W, AEC-Q200 Grade 0, 0402", Manufacturer=Vishay-Dale, Power_W=63mW, Supplier Part Number 1=541-4.7JCT-ND, Tempco="200 ppm/C", Tolerance_%=5%, Value2=0.063W, Value_Code=4R70, ValueDisplayed=4.7
R3 R7: library part CMP-0026822-3, "RES, 0, 5%, 0.063 W, AEC-Q200 Grade 0, 0402", Manufacturer=Vishay-Dale, Power_W=63mW, Supplier Part Number 1=541-0.0JCT-ND, Tempco="200 ppm/C", Tolerance_%=5%, Value2=0.063W, Value_Code=0000, ValueDisplayed=DNP
R4 R10: library part CMP-0026936-3, "RES, 47, 5%, 0.063 W, AEC-Q200 Grade 0, 0402", Manufacturer=Vishay-Dale, Power_W=63mW, Supplier Part Number 1=541-47JCT-ND, Tempco="200 ppm/C", Tolerance_%=5%, Value2=0.063W, Value_Code=47R0, ValueDisplayed=47
R5 R8: library part CMP-0026764-1, "RES, 10.0, 1%, 0.063 W, AEC-Q200 Grade 0, 0402", Manufacturer="Stackpole Electronics Inc", Power_W=63mW, Supplier Part Number 1=RMCF0402JT10R0CT-ND, Tempco="100 ppm/C", Tolerance_%=1%, Value2=0.063W, Value_Code=10R0, ValueDisplayed=10.0
R6 R9 R14: library part CMP-0026822-3, "RES, 0, 5%, 0.063 W, AEC-Q200 Grade 0, 0402", Manufacturer=Vishay-Dale, Power_W=63mW, Supplier Part Number 1=541-0.0JCT-ND, Tempco="200 ppm/C", Tolerance_%=5%, Value2=0.063W, Value_Code=0000, ValueDisplayed=0
R11: library part CMP-0015865-2, "RES, 0, 5%, 1.5 W, AEC-Q200 Grade 0, 2512", Manufacturer=Vishay-Dale, Power_W=1.5W, Supplier Part Number 1=541-0.0RBCT-ND, Tempco=ppm/C, Tolerance_%=5%, Value_Code=0000, ValueDisplayed=0
R12: library part CMP-0020547-3, "RES, 3.3, 5%, 0.125 W, AEC-Q200 Grade 0, 0805", Manufacturer=Vishay-Dale, Power_W=125mW, Supplier Part Number 1=541-3.3ACT-ND, Tempco="200 ppm/C", Tolerance_%=5%, Value2=0.125W, Value_Code=3R30, ValueDisplayed=3.3
R13: library part CMP-0022200-4, "RES, 200 k, 1%, 0.1 W, AEC-Q200 Grade 0, 0603", Manufacturer=Vishay-Dale, Power_W=100mW, Supplier Part Number 1=541-200KHCT-ND, Tempco="100 ppm/C", Tolerance_%=1%, Value2=0.1W, Value_Code=200k
R15: library part CMP-0026488-2, "RES, 619 k, 1%, 0.063 W, AEC-Q200 Grade 0, 0402", Manufacturer=Vishay-Dale, Power_W=63mW, Supplier Part Number 1=541-619KLCT-ND, Tempco="100 ppm/C", Tolerance_%=1%, Value2=0.063W, Value_Code=619k
R16: library part CMP-0026201-2, "RES, 25.5 k, 1%, 0.063 W, AEC-Q200 Grade 0, 0402", Manufacturer=Vishay-Dale, Power_W=63mW, Supplier Part Number 1=541-25.5KLCT-ND, Tempco="100 ppm/C", Tolerance_%=1%, Value2=0.063W, Value_Code=25k5, ValueDisplayed=25.5k
R17 R19: library part CMP-0025990-3, "RES, 12.0 k, 1%, 0.063 W, AEC-Q200 Grade 0, 0402", Manufacturer=Vishay-Dale, Power_W=63mW, Supplier Part Number 1=541-12.0KLCT-ND, Tempco="100 ppm/C", Tolerance_%=1%, Value2=0.063W, Value_Code=12k0, ValueDisplayed=12.0k
R18: library part CMP-0026952-5, "RES, 5.6 k, 5%, 0.063 W, AEC-Q200 Grade 0, 0402", Manufacturer=Vishay-Dale, Power_W=63mW, Supplier Part Number 1=541-5.6KJCT-ND, Tempco="200 ppm/C", Tolerance_%=5%, Value2=0.063W, Value_Code=5k60, ValueDisplayed=5.6k
R20: library part CMP-0026578-2, "RES, 84.5 k, 1%, 0.063 W, AEC-Q200 Grade 0, 0402", Manufacturer=Vishay-Dale, Power_W=63mW, Supplier Part Number 1=541-84.5KLCT-ND, Tempco="100 ppm/C", Tolerance_%=1%, Value2=0.063W, Value_Code=84k5, ValueDisplayed=84.5k
R21: library part CMP-0026051-3, "RES, 17.8 k, 1%, 0.063 W, AEC-Q200 Grade 0, 0402", Manufacturer=Vishay-Dale, Power_W=63mW, Supplier Part Number 1=541-17.8KLCT-ND, Tempco="100 ppm/C", Tolerance_%=1%, Value2=0.063W, Value_Code=17k8, ValueDisplayed=17.8k
U1: library part CMP-0097820-2, Manufacturer="Texas Instruments", Operating Temperature Range=to
U2: library part CMP-0095064-1, Digikey Part Number=296-ISO6720BDRCT-ND, Manufacturer="Texas Instruments", Max Supply Voltage=5.5V, Min Supply Voltage=1.71V, Mouser Part Number=595-ISO6720BDR, Operating Temperature Range="-40°C to +125°C"
U3: library part CMP-0045831-1, "Hex Schmitt-Trigger Inverters, NS0014A, LARGE T&R", F @ Nom Voltage(Max)(Mhz)=100, Generic Part Number=SN74AC14, ICC @ Nom Voltage(Max)(mA)=0.02, Manufacturer="Texas Instruments", Operating Temperature Range(C)="-40 to 85", Rating=Catalog, tpd @ Nom Voltage(Max)(ns)=15,11, Voltage(Nom)(V)=3.3,5
U4: library part CMP-0090388-1, "Basic Isolation Hall-Effect Current Sensor", Current Sensitivity=50mV/A, Manufacturer="Texas Instruments", Operating Temperature Range=to
U5: library part CMP-0860105-1, "Small Size, Nanopower, Low-Voltage Comparators, DGK0008A (VSSOP-8)", Alternate Manufacturer="Texas Instruments", Alternate PartNumber=TLV7032DGKT
U6: library part CMP-0089687-1, "3-V to 17-V, Synchronous Buck Converters in 1.6 mm x 2.1 mm SOT583 Package", Manufacturer="Texas Instruments", Max Supply Voltage=17V, Min Supply Voltage=3V, Nominal Supply Current=8mA, Operating Temperature Range="-40°C to +150°C", Output Voltage=0.4-5.5V, Switching Frequency=2.5MHz
ZZ1: library part CMP-0003616-3
ZZ2: library part CMP-0077236-1
ZZ3: library part CMP-0077237-1
ZZ4: library part CMP-0077238-1

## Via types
v1: diameter 0.5, hole 0.2, Top Layer to Bottom Layer, tented both sides, 360 vias

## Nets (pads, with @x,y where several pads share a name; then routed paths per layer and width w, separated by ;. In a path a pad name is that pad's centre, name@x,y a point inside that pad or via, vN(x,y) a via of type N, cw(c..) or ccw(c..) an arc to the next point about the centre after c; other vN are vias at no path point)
3V3: C8.1 C9.1 J1.1 U2.1 | length 16.2
  Top Layer w0.254: C9.1@15.95,45.2 C9.1@16,45.15 ; U2.1@16,43.25 C9.1@16,45.15 ; J1.1@28.65,49 21.8,49 18,45.2 C8.1@17.5,45.2 17.45,45.15 C9.1@16,45.15
3V3_AMP_CS: C31.1 C33.1 J1.3 R16.2 R18.2 U4.8 U5.8 | length 90.8
  Top Layer w0.254: U5.8@50.025,10.275 49.9,10.15 C31.1@49.9,8.75 47.5,8.75 46.9,9.35 R18.2@46.9,10.5 46.25,10.5 45.75,11 45.75,12.675 46.25,13.175 54.373,13.175 55.448,14.25 57.25,14.25 57.5,14 R16.2@57.5,13.1 57.6,13 v1(58.3,13) ; U4.8@60.955,21.8 C33.1@60.955,19.35 61.089,19.484 v1(61.75,19.484)
  Bottom Layer w0.254: J1.3@33.73,49 33.73,49.46 34.52,50.25 55.5,50.25 59.5,46.25 59.5,19.5 ; v1(58.3,13) 59.5,14.2 59.5,19.5 ; v1(61.75,19.484) 59.516,19.484 59.5,19.5
5V: C6.1 C7.1 C10.1 C11.1 C20.1 C26.1 C29.1 C32.1 L2.2 R1.2 R15.2 U2.8 U3.14 U6.3 | length 47.5
  Top Layer w0.254: C11.1@21.2,45.2 C11.1@21.25,45.15 ; U2.8@21.45,43.25 21.45,44.95 C11.1@21.25,45.15 ; C10.1@22.75,45.2 22.7,45.15 v1(21.975,45.15) C11.1@21.25,45.15 ; U3.14@44.975,43.56 45.4,43.985 C20.1@45.4,45.5 45.45,45.55 v1(45.45,46.25) C29.1@45.45,47
  Top Layer w0.4: v1(32.3,12) 32.7,12.4 C6.1@32.7,13.102 32.5,13.302 R1.2@32.5,14.502 C7.1@33.75,14.502
  Bottom Layer w0.254: v1(21.975,45.15) 26.284,40.841 v1(29.902,40.841) ; 29.406,38.155 29.406,37.219 29.875,36.75 37.7,36.75 45.45,44.5 v1(45.45,46.25) ; 29.52,37.73 R15.2@30.9,37.73 ; C32.1@30.9,40.5 31.05,40.35 C26.1@32.5,40.35 32.65,40.5 U6.3@33.835,40.5
  other v1: 29.902,40.25
AGND: C6.2 C7.2 C10.2 C11.2 C13.2 C16.2 C17.2 C18.2 C20.2 C25.2 C26.2 C29.2 C30.2 C32.2 R20.1 R21.1 U1.15 U2.5 U3.7 U6.5 | length 27.6
  Top Layer w0.254: C11.2@21.25,46.35 21.25,46.5 v1(21.75,47) 22.55,47 C10.2@22.75,46.8 ; U2.5@21.45,39.44 v1(22.7,39.44) ; 28.273,16.102 C17.2@29.65,16.102 ; 28.4,13.602 C16.2@29.65,13.602 ; U1.15@32.75,17.602 32.75,16.702 C7.2@33.75,15.702 34.9,15.702 ; C6.2@34.3,13.102 35.648,13.102 ; v1(36.25,35.94) U3.7@37.525,35.94 ; C29.2@47.05,47 47.05,45.95 C20.2@46.6,45.5 47.25,45.5 48,44.75 C18.2@48,43.85 ; C13.2@47.9,35.55 C13.2@48,35.65 48.073,35.577 v1(48.697,35.577)
  Bottom Layer w0.254: v1(35.315,41.655) U6.5@35.315,41 ; R21.1@37.075,37.9 36.925,37.75 R20.1@34.925,37.75 34.52,38.155 34.52,40.841 34.679,41 U6.5@35.315,41 ; C30.2@38.575,41.75 38.425,41.6 C25.2@37.075,41.6 36.475,41 U6.5@35.315,41
  other v1: 26.874,13.923 36.38,16.014 31.875,39.25 47.625,45.125
AMP_CS_FAULT: D4.1 D5.1 J4.5 | length 9.1
  Top Layer w0.254: v1(45.75,5.75) D4.1@46.95,5.75 47,5.8 D5.1@47,7.25
  Bottom Layer w0.254: J4.5@41.06,1.75 45.06,5.75 v1(45.75,5.75)
AMP_OFB: C24.1 J4.3 R14.1 U5.2 U5.5 | length 43.2
  Top Layer w0.254: J4.3@35.98,1.75 37.98,3.75 51.75,3.75 57.95,9.95 ; U5.5@50.025,12.225 51.775,12.225 53.075,10.925 U5.2@54.475,10.925 56.975,10.925 57.95,9.95 ; R14.1@59.685,18.15 59.685,16.785 C24.1@59.65,16.75 59.65,11.65 57.95,9.95
AMP_OSW: J4.1 R13.1 | length 37.3
  Top Layer w0.254: R13.1@54.8,23.7 54.8,23.302 v1(55.65,22.452)
  02IS01 w0.254: J4.1@30.9,1.75 32.986,3.836 32.986,5.392 33,5.406 33,5.5 42.155,14.655 50.234,14.655 55.65,20.071 v1(55.65,22.452)
AMP_OUT: C22.1 J3.3 R12.2 U4.1 U4.2
  other v1: 63.05,27.57 63.9,27.57 64.75,27.57 65.6,27.57 66.45,27.57 63.05,28.25 63.9,28.25 64.75,28.25 65.6,28.25 66.45,28.25 60.5,29 61.35,29 62.2,29 63.05,29 63.9,29 64.75,29 65.6,29 66.45,29 67.3,29 68.15,29 60.5,29.68 61.35,29.68 62.2,29.68 63.05,29.68 63.9,29.68 64.75,29.68 65.6,29.68 66.45,29.68 67.3,29.68 68.15,29.68
AMP_VFB: C21.1 D3.1 J4.2 Q1.1 Q1.2 Q1.3 R11.2 | length 46.1
  Top Layer w0.254: 48.668,26.968 48.668,24.982 C21.1@49.95,23.7 50.794,22.856 54.346,22.856 v1(54.75,22.452)
  02IS01 w0.254: J4.2@33.44,1.75 33.44,5.19 42.173,13.923 50.189,13.923 56.227,19.961 56.227,22.691 55.889,23.029 55.306,23.029 54.75,22.473 v1(54.75,22.452)
  other v1: 45.1,27.75 45.95,27.75 46.8,27.75 47.65,27.75 48.5,27.75 45.1,28.5 45.95,28.5 46.8,28.5 47.65,28.5 48.5,28.5
Audio_signal: Audio_In.1 R9.1 | length 11.6
  Top Layer w0.254: Audio_In.1@3.2,35 4.75,35 10.5,40.75 R9.1@12.4,40.75
Empty: R7.1 TP5.1 | length 10.6
  Top Layer w0.254: TP5.1@3.25,38.48 7.23,38.48 10.75,42 R7.1@12.4,42
GND1: C8.2 C9.2 GND.1 U2.4 | length 2.8
  Top Layer w0.254: v1(14.75,39.44) U2.4@16,39.44 ; C9.2@16,46.675 16.125,46.8 C8.2@17.5,46.8
  other v1: 16.75,46.8
GND2: C24.2 C31.2 C33.2 R17.1 R19.1 U4.5 U4.6 U5.4 | length 11.1
  Top Layer w0.254: R19.1@46.9,11.75 v1(46.9,12.5) ; C31.2@51.1,8.75 v1(51.1,9.5) ; U5.4@54.475,12.225 55.35,13.1 R17.1@56.25,13.1 ; U4.5@57.145,21.8 v1(57.75,21.8) U4.6@58.415,21.8 58.45,21.765 C24.2@58.45,16.75 ; C33.2@60.955,18.15 60.955,17.045 v1(61,17)
  other v1: 55.306,13
HB: R2.1 U1.10 | length 2.1
  Top Layer w0.254: 29.25,18.5 29.373,18.377 U1.10@29.975,18.377
  Top Layer w0.5: R2.1@28.1,19 28.75,19 29.25,18.5
HI: C17.1 HI.1 R5.2 U1.12 | length 27.2
  Top Layer w0.254: R5.2@30.85,14.852 C17.1@30.85,16.102 30.85,16.652 v1(31.05,16.852) 31.25,17.052 U1.12@31.25,17.602
  02IS01 w0.254: HI.1@13.5,1.75 13.5,2.578 27.774,16.852 v1(31.05,16.852)
HS: C12.2 U1.11 | length 2.1
  Top Layer w0.254: C12.2@27.85,17.802 C12.2@27.875,17.827
  Top Layer w0.4: C12.2@28.1,17.802 29.925,17.802 30.075,17.652
LI: C16.1 LI.1 R8.2 U1.13 | length 22.3
  Top Layer w0.254: v1(30.85,11.625) R8.2@30.85,12.352 C16.1@30.85,13.602 31.75,14.502 U1.13@31.75,17.602
  02IS01 w0.254: LI.1@19,1.75 24.75,7.5 26.725,7.5 v1(30.85,11.625)
NetC12_1: C12.1 R2.2 | length 1.2
  Top Layer w0.5: C12.1@26.9,17.802 R2.2@26.9,19
NetC13_1: C13.1 D1.1 R4.2 U3.9 | length 6.4
  Top Layer w0.254: U3.9@44.975,37.21 47.64,37.21 C13.1@48,36.85 48.15,37 R4.2@49.65,37 49.7,36.95 D1.1@49.7,35.5
NetC18_1: C18.1 D2.1 R10.2 U3.13 | length 6.4
  Top Layer w0.254: U3.13@44.975,42.29 47.64,42.29 C18.1@48,42.65 49.5,42.65 R10.2@49.65,42.5 49.7,42.55 D2.1@49.7,44
NetC21_2: C21.2 Q1.4 R13.2 | length 4.9
  Top Layer w0.254: Q1.4@49.45,25.89 49.712,25.89 51.55,24.052 C21.2@51.55,23.7 R13.2@53.2,23.7
NetC23_1: C23.1 R12.1
NetD1_2: D1.2 R3.2 R4.1 R6.2 | length 23.5
  Top Layer w0.254: R6.2@33.65,39.75 R3.2@33.65,37.21 33.65,36 34.9,34.75 50.5,34.75 50.8,35.05 D1.2@50.8,35.5 50.85,35.55 R4.1@50.85,37
NetD2_2: D2.2 R10.1 U3.2 U3.3 | length 20.3
  Top Layer w0.254: U3.3@37.525,41.02 36.48,41.02 36.25,41.25 v1(36.25,41.655) 36.25,42.06 36.48,42.29 U3.2@37.525,42.29 ; D2.2@50.8,44 50.85,43.95 v1(50.85,43.225) R10.1@50.85,42.5
  02IS01 w0.254: v1(36.25,41.655) 41.377,41.655 42.947,43.225 v1(50.85,43.225)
